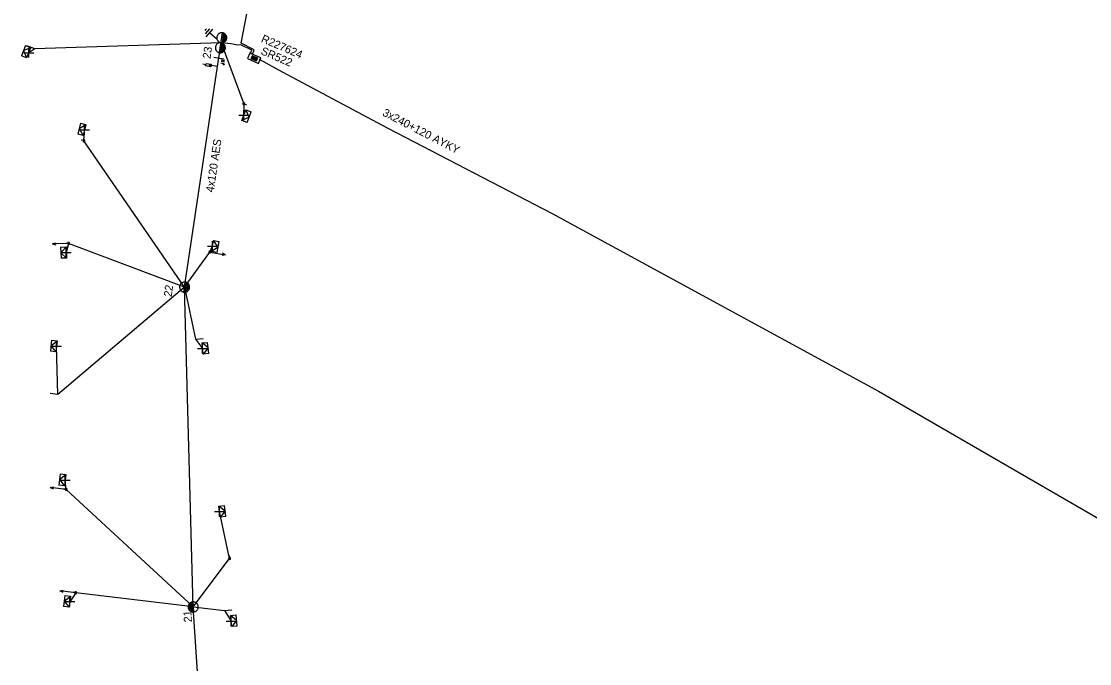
# Model space of a CAD drawing. Extents: x -544780 to -541582, y -1198995 to -1196551.
# Drawn here: x -543835.9 to -543702.5, y -1196914.3 to -1196834.2 of the extents above; entities that cross this region are included whole.
import ezdxf

# ---------------------------------------------------------------- set-up
doc = ezdxf.new("R2010")
doc.units = 0
for name, color, linetype in [('Vrstva 1', 7, 'Continuous'), ('Vrstva 13', 7, 'Continuous'), ('Vrstva 14', 7, 'Continuous'), ('Vrstva 15', 7, 'Continuous'), ('Vrstva 16', 7, 'Continuous'), ('Vrstva 18', 7, 'Continuous'), ('Vrstva 2', 7, 'Continuous'), ('Vrstva 28', 7, 'Continuous'), ('Vrstva 29', 7, 'Continuous'), ('Vrstva 30', 7, 'Continuous'), ('Vrstva 31', 7, 'Continuous'), ('Vrstva 34', 7, 'Continuous'), ('Vrstva 5', 7, 'Continuous'), ('Vrstva 50', 7, 'Continuous'), ('Vrstva 51', 7, 'Continuous'), ('Vrstva 54', 7, 'Continuous'), ('Vrstva 6', 7, 'Continuous'), ('Vrstva 8', 7, 'Continuous'), ('Vrstva 9', 7, 'Continuous')]:
    doc.layers.add(name, color=color, linetype=linetype)

# ---------------------------------------------------------------- blocks, each defined once
blk = doc.blocks.new('NN560')
at = {"layer": 'Vrstva 2'}
for points in [[(2, 0), (1.59, 0.14)], [(0, 0), (2, 0)], [(2, 0), (1.59, -0.13)]]:
    blk.add_lwpolyline(points, dxfattribs=at)
blk = doc.blocks.new('NN840')
at = {"layer": 'Vrstva 15'}
for points in [[(0, 0.62), (0, -0.63)], [(-0.75, -0.71), (-0.75, -0.66)], [(-0.73, -0.76), (-0.75, -0.71)], [(-0.66, -0.8), (-0.73, -0.76)], [(-0.63, -0.8), (-0.66, -0.8)], [(-0.56, -0.76), (-0.63, -0.8)], [(-0.54, -0.71), (-0.56, -0.76)], [(-0.54, -0.38), (-0.54, -0.71)], [(-0.33, -0.38), (-0.33, -0.8)], [(-0.33, -0.64), (-0.13, -0.38)], [(-0.26, -0.56), (-0.09, -0.8)]]:
    blk.add_lwpolyline(points, dxfattribs=at)
blk = doc.blocks.new('NN800')
at = {"layer": 'Vrstva 1'}
for points in [[(-0.44, 0.44), (0.44, -0.44)], [(-0.44, -0.44), (0.44, 0.44)]]:
    blk.add_lwpolyline(points, dxfattribs=at)
blk = doc.blocks.new('NN820')
at = {"layer": 'Vrstva 13'}
for points in [[(0, 0), (0, -1.05)], [(-0.16, -0.81), (0.16, -0.81)], [(-0.16, -1.47), (-0.16, -0.81)], [(0, -1.05), (-0.06, -0.93)], [(0, -1.05), (0.06, -0.93)], [(0.16, -0.81), (0.16, -1.47)], [(0.16, -1.47), (-0.16, -1.47)], [(0, -1.47), (0, -1.87)]]:
    blk.add_lwpolyline(points, dxfattribs=at)
blk = doc.blocks.new('NN620')
at = {"layer": 'Vrstva 8'}
for points in [[(0.75, 0), (-0.75, 0)], [(-0.75, 0), (-0.75, -0.75)], [(0.75, -0.75), (0.75, 0)], [(-0.75, -0.75), (0.75, -0.75)], [(0.37, -0.18), (-0.38, -0.18)], [(-0.38, -0.18), (-0.38, -0.56)], [(-0.38, -0.56), (0.37, -0.56)], [(0.32, -0.23), (-0.33, -0.23)], [(-0.33, -0.23), (-0.33, -0.51)], [(-0.33, -0.51), (0.32, -0.51)], [(0.27, -0.27), (-0.28, -0.27)], [(-0.28, -0.27), (-0.28, -0.46)], [(-0.28, -0.46), (0.27, -0.46)], [(0.23, -0.32), (-0.23, -0.32)], [(-0.23, -0.32), (-0.23, -0.42)], [(-0.23, -0.42), (0.23, -0.42)], [(-0.19, -0.37), (0.19, -0.37)], [(0.23, -0.42), (0.23, -0.32)], [(0.27, -0.46), (0.27, -0.27)], [(0.32, -0.51), (0.32, -0.23)], [(0.37, -0.56), (0.37, -0.18)]]:
    blk.add_lwpolyline(points, dxfattribs=at)
blk = doc.blocks.new('NN630')
at = {"layer": 'Vrstva 9'}
for points in [[(0, -0.7), (-0.7, 0)], [(-0.7, -0.7), (-0.7, 0), (0.7, 0), (0.7, -0.7)], [(-0.7, -0.7), (0.7, -0.7)], [(0, -0.7), (0.7, 0)]]:
    blk.add_lwpolyline(points, dxfattribs=at)
blk = doc.blocks.new('NN810')
at = {"layer": 'Vrstva 14'}
for points in [[(0, -0.64), (0, -1.89)], [(0.63, -1.89), (-0.62, -1.89)], [(0.39, -2.2), (-0.4, -2.2)], [(0, -2.52), (-0.12, -2.52)], [(0.14, -2.52), (0, -2.52)]]:
    blk.add_lwpolyline(points, dxfattribs=at)
blk = doc.blocks.new('NN500')
at = {"layer": 'Vrstva 2'}
for points in [[(0, -0.24), (0.02, -0.23), (0.05, -0.23), (0.07, -0.22), (0.09, -0.22), (0.12, -0.2), (0.14, -0.19), (0.16, -0.18), (0.17, -0.16), (0.19, -0.14), (0.2, -0.12), (0.21, -0.1), (0.22, -0.07), (0.23, -0.05), (0.23, -0.02), (0.23, 0), (0.23, 0.02), (0.23, 0.05), (0.22, 0.07), (0.21, 0.1), (0.2, 0.12), (0.19, 0.14), (0.17, 0.16), (0.16, 0.17), (0.14, 0.19), (0.12, 0.2), (0.09, 0.21), (0.07, 0.22), (0.05, 0.23), (0.02, 0.23), (0, 0.23), (-0.03, 0.23), (-0.05, 0.23), (-0.07, 0.22), (-0.1, 0.21), (-0.12, 0.2), (-0.14, 0.19), (-0.16, 0.17), (-0.18, 0.16), (-0.19, 0.14), (-0.2, 0.12), (-0.22, 0.1), (-0.22, 0.07), (-0.23, 0.05), (-0.23, 0.02), (-0.24, 0), (-0.23, -0.02), (-0.23, -0.05), (-0.22, -0.07), (-0.22, -0.1), (-0.2, -0.12), (-0.19, -0.14), (-0.18, -0.16), (-0.16, -0.18), (-0.14, -0.19), (-0.12, -0.2), (-0.1, -0.22), (-0.07, -0.22), (-0.05, -0.23), (-0.03, -0.23), (0, -0.24)], [(0, -0.24), (0.02, -0.23), (0.05, -0.23), (0.07, -0.22), (0.09, -0.22), (0.12, -0.2), (0.14, -0.19), (0.16, -0.18), (0.17, -0.16), (0.19, -0.14), (0.2, -0.12), (0.21, -0.1), (0.22, -0.07), (0.23, -0.05), (0.23, -0.02), (0.23, 0), (0.23, 0.02), (0.23, 0.05), (0.22, 0.07), (0.21, 0.1), (0.2, 0.12), (0.19, 0.14), (0.17, 0.16), (0.16, 0.17), (0.14, 0.19), (0.12, 0.2), (0.09, 0.21), (0.07, 0.22), (0.05, 0.23), (0.02, 0.23), (0, 0.23), (-0.03, 0.23), (-0.05, 0.23), (-0.07, 0.22), (-0.1, 0.21), (-0.12, 0.2), (-0.14, 0.19), (-0.16, 0.17), (-0.18, 0.16), (-0.19, 0.14), (-0.2, 0.12), (-0.22, 0.1), (-0.22, 0.07), (-0.23, 0.05), (-0.23, 0.02), (-0.24, 0), (-0.23, -0.02), (-0.23, -0.05), (-0.22, -0.07), (-0.22, -0.1), (-0.2, -0.12), (-0.19, -0.14), (-0.18, -0.16), (-0.16, -0.18), (-0.14, -0.19), (-0.12, -0.2), (-0.1, -0.22), (-0.07, -0.22), (-0.05, -0.23), (-0.03, -0.23), (0, -0.24)], [(0, -0.21), (0.02, -0.2), (0.04, -0.2), (0.06, -0.2), (0.08, -0.19), (0.1, -0.18), (0.12, -0.17), (0.14, -0.15), (0.15, -0.14), (0.16, -0.12), (0.18, -0.1), (0.19, -0.08), (0.19, -0.06), (0.2, -0.04), (0.2, -0.02), (0.2, 0), (0.2, 0.02), (0.2, 0.04), (0.19, 0.06), (0.19, 0.08), (0.18, 0.1), (0.16, 0.12), (0.15, 0.14), (0.14, 0.15), (0.12, 0.17), (0.1, 0.18), (0.08, 0.19), (0.06, 0.19), (0.04, 0.2), (0.02, 0.2), (0, 0.2), (-0.02, 0.2), (-0.04, 0.2), (-0.06, 0.19), (-0.08, 0.19), (-0.1, 0.18), (-0.12, 0.17), (-0.14, 0.15), (-0.15, 0.14), (-0.17, 0.12), (-0.18, 0.1), (-0.19, 0.08), (-0.2, 0.06), (-0.2, 0.04), (-0.21, 0.02), (-0.21, 0), (-0.21, -0.02), (-0.2, -0.04), (-0.2, -0.06), (-0.19, -0.08), (-0.18, -0.1), (-0.17, -0.12), (-0.15, -0.14), (-0.14, -0.15), (-0.12, -0.17), (-0.1, -0.18), (-0.08, -0.19), (-0.06, -0.2), (-0.04, -0.2), (-0.02, -0.2), (0, -0.21)], [(0, -0.18), (0.02, -0.18), (0.04, -0.17), (0.05, -0.17), (0.07, -0.16), (0.09, -0.15), (0.1, -0.14), (0.12, -0.13), (0.13, -0.12), (0.14, -0.1), (0.15, -0.09), (0.16, -0.07), (0.17, -0.05), (0.17, -0.04), (0.17, -0.02), (0.17, 0), (0.17, 0.02), (0.17, 0.04), (0.17, 0.05), (0.16, 0.07), (0.15, 0.09), (0.14, 0.1), (0.13, 0.12), (0.12, 0.13), (0.1, 0.14), (0.09, 0.15), (0.07, 0.16), (0.05, 0.17), (0.04, 0.17), (0.02, 0.17), (0, 0.18), (-0.02, 0.17), (-0.04, 0.17), (-0.06, 0.17), (-0.07, 0.16), (-0.09, 0.15), (-0.1, 0.14), (-0.12, 0.13), (-0.13, 0.12), (-0.14, 0.1), (-0.15, 0.09), (-0.16, 0.07), (-0.17, 0.05), (-0.17, 0.04), (-0.18, 0.02), (-0.18, 0), (-0.18, -0.02), (-0.17, -0.04), (-0.17, -0.05), (-0.16, -0.07), (-0.15, -0.09), (-0.14, -0.1), (-0.13, -0.12), (-0.12, -0.13), (-0.1, -0.14), (-0.09, -0.15), (-0.07, -0.16), (-0.06, -0.17), (-0.04, -0.17), (-0.02, -0.18), (0, -0.18)], [(0, -0.15), (0.01, -0.15), (0.03, -0.14), (0.04, -0.14), (0.06, -0.13), (0.07, -0.13), (0.08, -0.12), (0.1, -0.11), (0.11, -0.1), (0.12, -0.09), (0.13, -0.07), (0.13, -0.06), (0.14, -0.05), (0.14, -0.03), (0.14, -0.02), (0.14, 0), (0.14, 0.01), (0.14, 0.03), (0.14, 0.04), (0.13, 0.06), (0.13, 0.07), (0.12, 0.09), (0.11, 0.1), (0.1, 0.11), (0.08, 0.12), (0.07, 0.13), (0.06, 0.13), (0.04, 0.14), (0.03, 0.14), (0.01, 0.14), (0, 0.15), (-0.02, 0.14), (-0.03, 0.14), (-0.05, 0.14), (-0.06, 0.13), (-0.07, 0.13), (-0.09, 0.12), (-0.1, 0.11), (-0.11, 0.1), (-0.12, 0.09), (-0.13, 0.07), (-0.13, 0.06), (-0.14, 0.04), (-0.14, 0.03), (-0.15, 0.01), (-0.15, 0), (-0.15, -0.02), (-0.14, -0.03), (-0.14, -0.05), (-0.13, -0.06), (-0.13, -0.07), (-0.12, -0.09), (-0.11, -0.1), (-0.1, -0.11), (-0.09, -0.12), (-0.07, -0.13), (-0.06, -0.13), (-0.05, -0.14), (-0.03, -0.14), (-0.02, -0.15), (0, -0.15)], [(0, -0.12), (0.01, -0.12), (0.02, -0.11), (0.03, -0.11), (0.05, -0.11), (0.06, -0.1), (0.07, -0.09), (0.08, -0.09), (0.09, -0.08), (0.09, -0.07), (0.1, -0.06), (0.11, -0.05), (0.11, -0.04), (0.11, -0.02), (0.11, -0.01), (0.12, 0), (0.11, 0.01), (0.11, 0.02), (0.11, 0.04), (0.11, 0.05), (0.1, 0.06), (0.09, 0.07), (0.09, 0.08), (0.08, 0.09), (0.07, 0.09), (0.06, 0.1), (0.05, 0.11), (0.03, 0.11), (0.02, 0.11), (0.01, 0.12), (0, 0.12), (-0.01, 0.12), (-0.03, 0.11), (-0.04, 0.11), (-0.05, 0.11), (-0.06, 0.1), (-0.07, 0.09), (-0.08, 0.09), (-0.09, 0.08), (-0.1, 0.07), (-0.1, 0.06), (-0.11, 0.05), (-0.11, 0.04), (-0.12, 0.02), (-0.12, 0.01), (-0.12, 0), (-0.12, -0.01), (-0.12, -0.02), (-0.11, -0.04), (-0.11, -0.05), (-0.1, -0.06), (-0.1, -0.07), (-0.09, -0.08), (-0.08, -0.09), (-0.07, -0.09), (-0.06, -0.1), (-0.05, -0.11), (-0.04, -0.11), (-0.03, -0.11), (-0.01, -0.12), (0, -0.12)], [(0, -0.09), (0.01, -0.09), (0.02, -0.09), (0.03, -0.08), (0.03, -0.08), (0.04, -0.08), (0.05, -0.07), (0.06, -0.07), (0.06, -0.06), (0.07, -0.05), (0.07, -0.04), (0.08, -0.04), (0.08, -0.03), (0.08, -0.02), (0.09, -0.01), (0.09, 0), (0.09, 0.01), (0.08, 0.02), (0.08, 0.03), (0.08, 0.03), (0.07, 0.04), (0.07, 0.05), (0.06, 0.06), (0.06, 0.06), (0.05, 0.07), (0.04, 0.07), (0.03, 0.08), (0.03, 0.08), (0.02, 0.08), (0.01, 0.09), (0, 0.09), (-0.01, 0.09), (-0.02, 0.08), (-0.03, 0.08), (-0.04, 0.08), (-0.04, 0.07), (-0.05, 0.07), (-0.06, 0.06), (-0.07, 0.06), (-0.07, 0.05), (-0.08, 0.04), (-0.08, 0.03), (-0.08, 0.03), (-0.09, 0.02), (-0.09, 0.01), (-0.09, 0), (-0.09, -0.01), (-0.09, -0.02), (-0.08, -0.03), (-0.08, -0.04), (-0.08, -0.04), (-0.07, -0.05), (-0.07, -0.06), (-0.06, -0.07), (-0.05, -0.07), (-0.04, -0.08), (-0.04, -0.08), (-0.03, -0.08), (-0.02, -0.09), (-0.01, -0.09), (0, -0.09)], [(0, -0.06), (0, -0.06), (0.01, -0.06), (0.02, -0.05), (0.02, -0.05), (0.03, -0.05), (0.03, -0.05), (0.04, -0.04), (0.04, -0.04), (0.05, -0.03), (0.05, -0.03), (0.05, -0.02), (0.05, -0.02), (0.05, -0.01), (0.06, -0.01), (0.06, 0), (0.06, 0.01), (0.05, 0.01), (0.05, 0.02), (0.05, 0.02), (0.05, 0.03), (0.05, 0.03), (0.04, 0.04), (0.04, 0.04), (0.03, 0.05), (0.03, 0.05), (0.02, 0.05), (0.02, 0.05), (0.01, 0.06), (0, 0.06), (0, 0.06), (-0.01, 0.06), (-0.01, 0.06), (-0.02, 0.05), (-0.02, 0.05), (-0.03, 0.05), (-0.03, 0.05), (-0.04, 0.04), (-0.04, 0.04), (-0.05, 0.03), (-0.05, 0.03), (-0.05, 0.02), (-0.06, 0.02), (-0.06, 0.01), (-0.06, 0.01), (-0.06, 0), (-0.06, -0.01), (-0.06, -0.01), (-0.06, -0.02), (-0.05, -0.02), (-0.05, -0.03), (-0.05, -0.03), (-0.04, -0.04), (-0.04, -0.04), (-0.03, -0.05), (-0.03, -0.05), (-0.02, -0.05), (-0.02, -0.05), (-0.01, -0.06), (-0.01, -0.06), (0, -0.06)], [(0, -0.03), (0, -0.03), (0, -0.03), (0.01, -0.03), (0.01, -0.03), (0.01, -0.02), (0.02, -0.02), (0.02, -0.02), (0.02, -0.02), (0.02, -0.02), (0.02, -0.01), (0.02, -0.01), (0.03, -0.01), (0.03, -0.01), (0.03, 0), (0.03, 0), (0.03, 0), (0.03, 0.01), (0.03, 0.01), (0.02, 0.01), (0.02, 0.01), (0.02, 0.02), (0.02, 0.02), (0.02, 0.02), (0.02, 0.02), (0.01, 0.02), (0.01, 0.02), (0.01, 0.03), (0, 0.03), (0, 0.03), (0, 0.03), (0, 0.03), (-0.01, 0.03), (-0.01, 0.03), (-0.01, 0.02), (-0.02, 0.02), (-0.02, 0.02), (-0.02, 0.02), (-0.02, 0.02), (-0.02, 0.02), (-0.03, 0.01), (-0.03, 0.01), (-0.03, 0.01), (-0.03, 0.01), (-0.03, 0), (-0.03, 0), (-0.03, 0), (-0.03, -0.01), (-0.03, -0.01), (-0.03, -0.01), (-0.03, -0.01), (-0.02, -0.02), (-0.02, -0.02), (-0.02, -0.02), (-0.02, -0.02), (-0.02, -0.02), (-0.01, -0.03), (-0.01, -0.03), (-0.01, -0.03), (0, -0.03), (0, -0.03)], [(0.23, 0), (0.7, 0)]]:
    blk.add_lwpolyline(points, dxfattribs=at)
blk = doc.blocks.new('NN510')
at = {"layer": 'Vrstva 2'}
blk.add_lwpolyline([(0, 0), (0, 0.94)], dxfattribs=at)
blk = doc.blocks.new('NN440')
at = {"layer": 'Vrstva 2'}
for points in [[(0.63, 0), (0.63, 0.06), (0.62, 0.13), (0.6, 0.19), (0.58, 0.25), (0.55, 0.31), (0.51, 0.37), (0.47, 0.42), (0.42, 0.46), (0.37, 0.51), (0.32, 0.54), (0.26, 0.57), (0.2, 0.59), (0.13, 0.61), (0.07, 0.62), (0, 0.63), (-0.06, 0.62), (-0.13, 0.61), (-0.19, 0.59), (-0.26, 0.57), (-0.31, 0.54), (-0.37, 0.51), (-0.42, 0.46), (-0.47, 0.42), (-0.51, 0.37), (-0.54, 0.31), (-0.57, 0.25), (-0.6, 0.19), (-0.62, 0.13), (-0.63, 0.06), (-0.63, 0), (-0.63, -0.07), (-0.62, -0.14), (-0.6, -0.2), (-0.57, -0.26), (-0.54, -0.32), (-0.51, -0.37), (-0.47, -0.43), (-0.42, -0.47), (-0.37, -0.51), (-0.31, -0.55), (-0.26, -0.58), (-0.19, -0.6), (-0.13, -0.62), (-0.06, -0.63), (0, -0.63), (0.07, -0.63), (0.13, -0.62), (0.2, -0.6), (0.26, -0.58), (0.32, -0.55), (0.37, -0.51), (0.42, -0.47), (0.47, -0.43), (0.51, -0.37), (0.55, -0.32), (0.58, -0.26), (0.6, -0.2), (0.62, -0.14), (0.63, -0.07), (0.63, 0)], [(-0.63, 0), (0.63, 0)], [(-0.6, -0.18), (0.57, -0.18)], [(-0.51, -0.32), (0.5, -0.32)], [(-0.37, -0.47), (0.35, -0.47)]]:
    blk.add_lwpolyline(points, dxfattribs=at)
blk = doc.blocks.new('NN450')
at = {"layer": 'Vrstva 2'}
for points in [[(0, 0), (0, 0.07), (-0.01, 0.13), (-0.03, 0.19), (-0.05, 0.25), (-0.08, 0.31), (-0.12, 0.37), (-0.16, 0.42), (-0.21, 0.46), (-0.26, 0.51), (-0.31, 0.54), (-0.37, 0.57), (-0.43, 0.59), (-0.5, 0.61), (-0.56, 0.62), (-0.63, 0.62), (-0.69, 0.62), (-0.75, 0.61), (-0.82, 0.59), (-0.88, 0.57), (-0.94, 0.54), (-0.99, 0.51), (-1.04, 0.46), (-1.09, 0.42), (-1.13, 0.37), (-1.17, 0.31), (-1.2, 0.25), (-1.22, 0.19), (-1.24, 0.13), (-1.25, 0.07), (-1.25, 0), (-1.25, -0.07), (-1.24, -0.13), (-1.22, -0.19), (-1.2, -0.25), (-1.17, -0.31), (-1.13, -0.37), (-1.09, -0.42), (-1.04, -0.46), (-0.99, -0.51), (-0.94, -0.54), (-0.88, -0.57), (-0.82, -0.59), (-0.75, -0.61), (-0.69, -0.62), (-0.62, -0.63), (-0.56, -0.62), (-0.5, -0.61), (-0.43, -0.59), (-0.37, -0.57), (-0.31, -0.54), (-0.26, -0.51), (-0.21, -0.46), (-0.16, -0.42), (-0.12, -0.37), (-0.08, -0.31), (-0.05, -0.25), (-0.03, -0.19), (-0.01, -0.13), (0, -0.07), (0, 0)], [(1.25, 0), (1.25, 0.07), (1.24, 0.13), (1.22, 0.19), (1.2, 0.25), (1.17, 0.31), (1.13, 0.37), (1.09, 0.42), (1.04, 0.46), (0.99, 0.51), (0.94, 0.54), (0.88, 0.57), (0.82, 0.59), (0.75, 0.61), (0.69, 0.62), (0.62, 0.62), (0.56, 0.62), (0.5, 0.61), (0.43, 0.59), (0.37, 0.57), (0.31, 0.54), (0.26, 0.51), (0.21, 0.46), (0.16, 0.42), (0.12, 0.37), (0.08, 0.31), (0.05, 0.25), (0.03, 0.19), (0.01, 0.13), (0, 0.07), (0, 0), (0, -0.07), (0.01, -0.13), (0.03, -0.19), (0.05, -0.25), (0.08, -0.31), (0.12, -0.37), (0.16, -0.42), (0.21, -0.46), (0.26, -0.51), (0.31, -0.54), (0.37, -0.57), (0.43, -0.59), (0.5, -0.61), (0.56, -0.62), (0.63, -0.63), (0.69, -0.62), (0.75, -0.61), (0.82, -0.59), (0.88, -0.57), (0.94, -0.54), (0.99, -0.51), (1.04, -0.46), (1.09, -0.42), (1.13, -0.37), (1.17, -0.31), (1.2, -0.25), (1.22, -0.19), (1.24, -0.13), (1.25, -0.07), (1.25, 0)], [(-1.25, 0), (1.25, 0)], [(-1.23, -0.16), (-0.02, -0.16)], [(-1.16, -0.32), (-0.09, -0.32)], [(-1.03, -0.47), (-0.22, -0.47)], [(0.02, -0.16), (1.23, -0.16)], [(0.09, -0.32), (1.16, -0.32)], [(0.22, -0.47), (1.03, -0.47)]]:
    blk.add_lwpolyline(points, dxfattribs=at)

msp = doc.modelspace()

# ---------------------------------------------------------------- linework, layer by layer
at = {"layer": 'Vrstva 5'}
for points in [[(-543807.05, -1196838.29), (-543806.83, -1196837.72), (-543808.48, -1196836.89), (-543804.99, -1196818.95), (-543805.93, -1196817.7), (-543806.92, -1196817.02), (-543807.98, -1196816.47), (-543816.43, -1196815.65), (-543818.51, -1196814.58), (-543825.14, -1196812.84), (-543828.11, -1196812.22), (-543828.58, -1196812.31)], [(-543807.31, -1196838.17), (-543807.13, -1196837.74), (-543808.5, -1196837.06), (-543808.95, -1196837.12), (-543809.72, -1196836.95), (-543810.97, -1196836.82)], [(-543806.23, -1196838.89), (-543803.33, -1196840.47), (-543790.13, -1196847.49), (-543769.61, -1196858.13), (-543728.87, -1196880.33), (-543698.49, -1196897.9), (-543698.36, -1196897.99), (-543697.32, -1196899.25)]]:
    msp.add_lwpolyline(points, dxfattribs=at)
at = {"layer": 'Vrstva 50'}
msp.add_lwpolyline([(-543812.73, -1196993.13), (-543810.73, -1196963.97), (-543811.75, -1196947.77), (-543814.46, -1196907.25), (-543815.53, -1196867.33), (-543811.42, -1196839.78), (-543810.97, -1196836.82)], dxfattribs=at)
at = {"layer": 'Vrstva 54'}
for points in [[(-543810.97, -1196836.82), (-543834.23, -1196837.6), (-543835, -1196838.06)], [(-543810.97, -1196836.82), (-543808.13, -1196844.44), (-543808.12, -1196845.86)], [(-543814.46, -1196907.25), (-543830.33, -1196892.58), (-543830.46, -1196891.43)], [(-543814.46, -1196907.25), (-543809.9, -1196901.2), (-543811.16, -1196895.36)], [(-543814.46, -1196907.25), (-543829.13, -1196905.48), (-543829.87, -1196906.6)], [(-543814.46, -1196907.25), (-543810.55, -1196907.7), (-543809.72, -1196909.02)]]:
    msp.add_lwpolyline(points, dxfattribs=at)
at = {"layer": 'Vrstva 8'}
for points in [[(-543815.53, -1196867.33), (-543828.1, -1196849.06), (-543828.02, -1196847.7)], [(-543815.53, -1196867.33), (-543830.02, -1196861.87), (-543830.3, -1196863.01)], [(-543815.53, -1196867.33), (-543812.39, -1196862.95), (-543812.04, -1196862.2)], [(-543815.53, -1196867.33), (-543831.38, -1196880.72), (-543831.52, -1196874.72)], [(-543815.53, -1196867.33), (-543814.15, -1196873.84), (-543813.28, -1196875)]]:
    msp.add_lwpolyline(points, dxfattribs=at)

# ---------------------------------------------------------------- block references
at = {"layer": 'Vrstva 13'}
for name, p, rotation in [('NN450', (-543810.97, -1196836.82), 81.80083054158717), ('NN510', (-543834.23, -1196837.6), 67.55328048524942), ('NN560', (-543830.02, -1196861.87), -177.9652693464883), ('NN560', (-543812.38, -1196862.95), -10.503363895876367), ('NN440', (-543815.53, -1196867.33), 81.9662583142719), ('NN510', (-543814.15, -1196873.84), -84.02998338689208), ('NN510', (-543831.38, -1196880.72), 83.32454443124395), ('NN560', (-543830.33, -1196892.58), 173.10334716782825), ('NN560', (-543829.13, -1196905.48), 173.10334717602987), ('NN440', (-543814.45, -1196907.25), -86.72739447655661), ('NN510', (-543810.55, -1196907.7), -83.7943583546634)]:
    msp.add_blockref(name, p, dxfattribs=dict(at, rotation=rotation))
for p, xscale, yscale, rotation in [((-543808.13, -1196844.44), 0.5, 0.5000000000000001, -21.47200002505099), ((-543828.1, -1196849.06), 0.49999999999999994, 0.5, 167.05899992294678), ((-543830.02, -1196861.87), 0.5, 0.49999999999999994, -177.9649999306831), ((-543812.38, -1196862.95), 0.49999999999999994, 0.4999999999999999, -10.503000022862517), ((-543830.33, -1196892.58), 0.5, 0.5, 173.10300000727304), ((-543809.9, -1196901.2), 0.49999999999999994, 0.5000000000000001, 95.87899999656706), ((-543829.13, -1196905.48), 0.5, 0.5, 173.10300000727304)]:
    msp.add_blockref('NN500', p, dxfattribs=dict(at, xscale=xscale, yscale=yscale, rotation=rotation))
at = {"layer": 'Vrstva 15', "rotation": -130.46606118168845}
msp.add_blockref('NN810', (-543810.97, -1196836.82), dxfattribs=at)
at = {"layer": 'Vrstva 16', "rotation": -98.49494716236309}
msp.add_blockref('NN820', (-543811.42, -1196839.78), dxfattribs=at)
at = {"layer": 'Vrstva 18', "rotation": 79.36575559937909}
msp.add_blockref('NN840', (-543811.26, -1196838.73), dxfattribs=at)
at = {"layer": 'Vrstva 28', "rotation": 156.590919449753}
msp.add_blockref('NN620', (-543806.97, -1196839.1), dxfattribs=at)
at = {"layer": 'Vrstva 31'}
for p, rotation in [((-543835, -1196838.06), -112.44671946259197), ((-543808.12, -1196845.86), 68.52771670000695), ((-543828.02, -1196847.7), -102.94118614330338), ((-543812.04, -1196862.2), 79.49360281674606), ((-543830.29, -1196863.01), -87.94235276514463), ((-543831.52, -1196874.72), -96.67545556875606), ((-543813.28, -1196875), 95.97001662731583), ((-543830.46, -1196891.43), -96.89665284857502), ((-543811.16, -1196895.36), 95.94266108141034), ((-543829.87, -1196906.6), -96.89665284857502), ((-543809.72, -1196909.02), 96.20564166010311)]:
    msp.add_blockref('NN630', p, dxfattribs=dict(at, rotation=rotation))
at = {"layer": 'Vrstva 34'}
for p, rotation in [((-543835, -1196838.06), 45), ((-543808.12, -1196845.86), 45), ((-543828.02, -1196847.7), 45.00000009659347), ((-543812.04, -1196862.2), 45.00000009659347), ((-543830.3, -1196863.01), 45), ((-543831.52, -1196874.72), 45), ((-543813.28, -1196875), 45), ((-543830.46, -1196891.43), 45), ((-543811.16, -1196895.36), 45), ((-543829.87, -1196906.59), 45), ((-543809.72, -1196909.02), 45)]:
    msp.add_blockref('NN800', p, dxfattribs=dict(at, rotation=rotation))

# ---------------------------------------------------------------- texts
at = {"layer": 'Vrstva 14'}
for s, rotation, p in [('23', 81.801, (-543812.3, -1196838.86)), ('22', 81.966, (-543817.15, -1196868.59)), ('21', 93.273, (-543814.61, -1196909.14))]:
    msp.add_text(s, height=1, rotation=rotation, dxfattribs=at).set_placement(p)
at = {"layer": 'Vrstva 29'}
msp.add_text('R227624', height=1, rotation=336.591, dxfattribs=at).set_placement((-543806.05, -1196836.68))
at = {"layer": 'Vrstva 30'}
msp.add_text('SR522', height=1, rotation=336.591, dxfattribs=at).set_placement((-543806.1, -1196838.21))
at = {"layer": 'Vrstva 51'}
msp.add_text('4x120 AES', height=1, rotation=81.505, dxfattribs=at).set_placement((-543811.9, -1196855.54))
at = {"layer": 'Vrstva 6'}
msp.add_text('3x240+120 AYKY', height=1, rotation=332.585, dxfattribs=at).set_placement((-543790.9, -1196845.86))

doc.saveas('drawing.dxf')
